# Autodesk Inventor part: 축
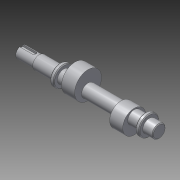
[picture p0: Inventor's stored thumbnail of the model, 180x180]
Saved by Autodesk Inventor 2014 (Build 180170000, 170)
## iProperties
Created: 2014-12
Part Number: 축
Material: 알루미늄 6061
Document SubType Name: Modeling
Designer: Owner
Density: 2.71 g/cm^3
Appearance: 알루미늄 - 평지
Mass: 170.354 g
Surface Area: 153.402 cm^2
Volume: 62.8614 cm^3
Author: Owner
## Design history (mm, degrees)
sketch "스케치1"
  geometry: L1 (0, 0)-(180, 0); L2 (0, 0)-(0, 7.5); L3 (0, 7.5)-(24, 7.5); L4 (24, 7.5)-(24, 8.5); L5 (24, 8.5)-(51, 8.5); L6 (51, 8.5)-(51, 13); L7 (51, 13)-(56, 13); L8 (56, 13)-(56, 8.5); L9 (56, 8.5)-(162, 8.5); L10 (162, 8.5)-(162, 13); L11 (162, 13)-(167, 13); L12 (167, 13)-(167, 8.5); L13 (167, 8.5)-(180, 8.5); L14 (180, 8.5)-(180, 0); 1 further point
  constraints: 28 end point, 9 parallel, 4 perpendicular, 2 horizontal alignment, 1 coincident, 1 horizontal
  dimensions: "d0" = 180 distance of L1.start L1.end; "d1" = 24 distance of L2.end L3.end; "d2" = 27 distance of L4.end L5.end; "d3" = 5 distance of L6.end L7.end; "d4" = 15 diameter of L3 L1; "d5" = 17 diameter of L5 L1; "d6" = 26 diameter of L7 L1; "d7" = 13 distance of L12.end L13.end; "d8" = 5 distance of L10.end L11.end; "d9" = 26 diameter of L11 L1
revolve "회전1" sketch "스케치1" stored, may be unused: angle "d10" = 90 deg
node "작업 평면1"
sketch "스케치2"
  geometry: C1 r 17.5 at (0, 6); 1 further point
  constraints: 1 centre point, 1 vertical alignment
  dimensions: "d12" = 6 distance of point (0, 0) C1.centre; "d13" = 35 diameter of C1
extrude "돌출1" join sketch "스케치2" distance "d14" = 17; taper "d15" = 0 deg
node "작업 평면3"
sketch "스케치3"
  geometry: C1 r 15 at (0, -5); 1 further point
  constraints: 1 centre point, 1 vertical alignment
  dimensions: "d17" = 5 distance of C1.centre point (0, 0); "d18" = 30 diameter of C1
extrude "돌출2" join sketch "스케치3" distance "d19" = 17; taper "d20" = 0 deg
node "작업 평면6"
sketch "스케치4"
  geometry: L1 (10.5, 0)-(5.5, 0); L2 (-12, -2.5)-(5.5, -2.5); L3 (5.5, 2.5)-(-12, 2.5); L4 (-12, -7.5)-(-12, 7.5) reference; A1 r 2.5 centre (5.5, 0) between (5.5, -2.5) and (5.5, 2.5); 2 further points
  constraints: 8 end point, 3 point on circle, 2 parallel, 2 point on line, 2 tangent, 1 centre point, 1 horizontal, 1 horizontal alignment, 1 midpoint
  dimensions: "d21" = 5 distance between parallel lines of L2 L3; "d22" = 20 dimension on A1 L4
extrude "돌출3" cut sketch "스케치4" distance "d23" = 3; taper "d24" = 0 deg
chamfer "모따기1" distance "d25" = 1; stored, may be unused: second distance "d26" = 2, angle "d27" = 45 deg
chamfer "모따기2" distance "d28" = 1; stored, may be unused: second distance "d29" = 2, angle "d30" = 45 deg
chamfer "모따기3" distance "d31" = 1; stored, may be unused: second distance "d32" = 2, angle "d33" = 45 deg
node "솔리드1"
other parameters: "d11" = 70.5, "d16" = 147.5
